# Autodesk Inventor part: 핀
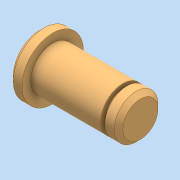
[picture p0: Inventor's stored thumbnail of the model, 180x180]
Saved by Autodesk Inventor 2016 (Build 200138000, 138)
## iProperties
Created: 2024-08
Part Number: 핀
Material: 일반
Document SubType Name: Modeling
Designer: pc-7
Density: 1 g/cm^3
Appearance: 기본값
Author: jhkim
Sending System: Autodesk Inventor 2025
Preprocessor: ST-DEVELOPER v20
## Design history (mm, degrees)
node "핀1"
node "솔리드2"
node "솔리드1"
